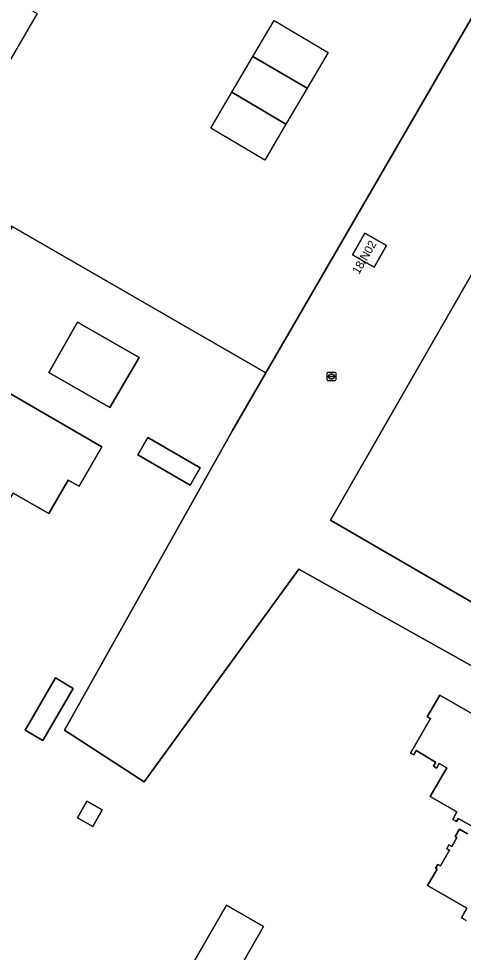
# Model space of a CAD drawing. Extents: x 156502 to 159075, y 384229 to 386100.
# Drawn here: x 157217.5 to 157270.5, y 385707.8 to 385818.9 of the extents above; entities that cross this region are included whole.
import ezdxf

# ---------------------------------------------------------------- set-up
doc = ezdxf.new("R2010")
doc.units = 0
for name, color, linetype in [('IMGEO_Erf', 7, 'Continuous'), ('IMGEO_Gemengd_bos', 7, 'Continuous'), ('IMGEO_Grasland_overig', 7, 'Continuous'), ('IMGEO_Hek', 7, 'Continuous'), ('IMGEO_Pand', 7, 'Continuous'), ('IMGEO_Pand_nummerreeks', 7, 'Continuous'), ('IMGEO_Pand_vergunning_verleend', 7, 'Continuous'), ('IMGEO_Rioolput', 7, 'Continuous')]:
    doc.layers.add(name, color=color, linetype=linetype)

msp = doc.modelspace()

# ---------------------------------------------------------------- linework, layer by layer
at = {"layer": 'IMGEO_Erf'}
for points in [[(157285.22, 385812.46), (157254.63, 385759.26), (157295.91, 385735.36)], [(157300.61, 385725.63), (157250.89, 385753.43), (157232.44, 385728.12), (157222.97, 385734.27), (157242.96, 385769.96), (157246.93, 385776.79), (157216.71, 385794.2), (157213.48, 385788.66), (157210.48, 385783.47), (157204.89, 385773.82), (157204.09, 385772.37), (157190.66, 385749.03), (157190.19, 385748.22), (157189.58, 385747.17), (157173.06, 385718.5), (157188.56, 385701.55)], [(157271.48, 385722.84), (157269.92, 385723.74), (157269.87, 385723.77), (157269.65, 385723.39), (157269.2, 385723.65), (157269.71, 385724.54), (157266.53, 385726.38), (157268.5, 385729.78), (157267.59, 385730.3), (157267.28, 385729.77), (157266.91, 385729.99), (157267.19, 385730.47), (157267.15, 385730.49), (157264.84, 385731.84), (157264.55, 385731.34), (157264.18, 385731.56), (157266.55, 385735.65), (157266.17, 385735.87), (157267.66, 385738.45), (157272.7, 385735.53)], [(157270.8, 385711.63), (157270.24, 385711.96), (157270.9, 385713.1), (157266.2, 385715.79), (157267.33, 385717.75), (157267.15, 385717.85), (157267.42, 385718.31), (157267.76, 385718.12), (157268.83, 385719.98), (157268.49, 385720.17), (157268.75, 385720.64), (157269.09, 385720.44), (157269.7, 385721.5), (157269.48, 385721.62), (157270, 385722.51), (157270.96, 385721.95)]]:
    msp.add_lwpolyline(points, dxfattribs=at)
for points in [[(157221.09, 385776.86), (157224.52, 385782.84), (157231.84, 385778.64), (157228.38, 385772.66)], [(157216.83, 385762.5), (157214.84, 385759.03), (157215.78, 385758.51), (157212.12, 385752.19), (157207.44, 385754.89), (157208.16, 385756.16), (157204.14, 385758.49), (157207.06, 385763.56), (157207.93, 385763.06), (157209.9, 385766.51), (157209.04, 385767.01), (157210.23, 385769.06), (157211.36, 385771.04), (157210.09, 385771.77), (157212.8, 385776.43), (157227.39, 385767.99), (157224.69, 385763.33), (157223.41, 385764.04), (157221.09, 385760.05)], [(157231.7, 385767.06), (157232.9, 385769.12), (157239.12, 385765.48), (157237.93, 385763.43)], [(157220.39, 385733.03), (157218.29, 385734.26), (157221.89, 385740.49), (157223.98, 385739.25)], [(157226.33, 385722.82), (157224.51, 385723.85), (157225.63, 385725.82), (157227.44, 385724.79)], [(157242.25, 385713.46), (157246.67, 385710.91), (157242.61, 385703.87), (157238.19, 385706.43)]]:
    msp.add_lwpolyline(points, close=True, dxfattribs=at)
at = {"layer": 'IMGEO_Gemengd_bos'}
for points in [[(157285.22, 385812.46), (157275.52, 385818.05), (157272.04, 385820.04), (157246.93, 385776.79), (157242.96, 385769.96), (157222.97, 385734.27), (157232.44, 385728.12), (157250.89, 385753.43), (157300.61, 385725.63), (157300.68, 385725.75), (157301.99, 385728.11), (157303.57, 385730.97), (157295.91, 385735.36), (157254.63, 385759.26)], [(157259.84, 385789.36), (157257.25, 385790.84), (157258.72, 385793.43), (157261.32, 385791.94)]]:
    msp.add_lwpolyline(points, close=True, dxfattribs=at)
at = {"layer": 'IMGEO_Grasland_overig'}
msp.add_lwpolyline([(157186.51, 385823.49), (157214.2, 385807.37), (157215.15, 385806.82), (157210.12, 385798.13), (157215.69, 385794.81), (157216.71, 385794.2), (157246.93, 385776.79), (157272.04, 385820.04)], dxfattribs=at)
at = {"layer": 'IMGEO_Hek'}
msp.add_lwpolyline([(157295.91, 385735.36), (157254.63, 385759.26), (157285.22, 385812.46)], dxfattribs=at)
at = {"layer": 'IMGEO_Pand'}
for points in [[(157259.84, 385789.36), (157261.32, 385791.94), (157258.72, 385793.43), (157257.25, 385790.84)], [(157231.84, 385778.64), (157224.52, 385782.84), (157221.09, 385776.86), (157228.38, 385772.66)], [(157227.39, 385767.99), (157212.8, 385776.43), (157210.09, 385771.77), (157211.36, 385771.04), (157210.23, 385769.06), (157209.04, 385767.01), (157209.9, 385766.51), (157207.93, 385763.06), (157207.06, 385763.56), (157204.14, 385758.49), (157208.16, 385756.16), (157207.44, 385754.89), (157212.12, 385752.19), (157215.78, 385758.51), (157214.84, 385759.03), (157216.83, 385762.5), (157221.09, 385760.05), (157223.41, 385764.04), (157224.69, 385763.33)], [(157232.9, 385769.12), (157231.7, 385767.06), (157237.93, 385763.43), (157239.12, 385765.48)], [(157221.89, 385740.49), (157218.29, 385734.26), (157220.39, 385733.03), (157223.98, 385739.25)], [(157224.51, 385723.85), (157226.33, 385722.82), (157227.44, 385724.79), (157225.63, 385725.82)], [(157246.67, 385710.91), (157242.25, 385713.46), (157238.19, 385706.43), (157242.61, 385703.87)]]:
    msp.add_lwpolyline(points, close=True, dxfattribs=at)
for points in [[(157272.7, 385735.53), (157267.66, 385738.45), (157266.17, 385735.87), (157266.55, 385735.65), (157264.18, 385731.56), (157264.55, 385731.34), (157264.84, 385731.84), (157267.15, 385730.49), (157267.19, 385730.47), (157266.91, 385729.99), (157267.28, 385729.77), (157267.59, 385730.3), (157268.5, 385729.78), (157266.53, 385726.38), (157269.71, 385724.54), (157269.2, 385723.65), (157269.65, 385723.39), (157269.87, 385723.77), (157269.92, 385723.74), (157271.48, 385722.84)], [(157270.96, 385721.95), (157270, 385722.51), (157269.48, 385721.62), (157269.7, 385721.5), (157269.09, 385720.44), (157268.75, 385720.64), (157268.49, 385720.17), (157268.83, 385719.98), (157267.76, 385718.12), (157267.42, 385718.31), (157267.15, 385717.85), (157267.33, 385717.75), (157266.2, 385715.79), (157270.9, 385713.1), (157270.24, 385711.96), (157270.8, 385711.63)]]:
    msp.add_lwpolyline(points, dxfattribs=at)
at = {"layer": 'IMGEO_Pand_vergunning_verleend'}
for points in [[(157204.02, 385820.18), (157207.73, 385826.55), (157209.87, 385825.3), (157216.64, 385821.35), (157219.71, 385819.56), (157216, 385813.2)], [(157245.41, 385814.46), (157247.93, 385818.72), (157254.37, 385814.92), (157251.86, 385810.66)], [(157242.9, 385810.2), (157245.41, 385814.46), (157251.86, 385810.66), (157249.34, 385806.39)], [(157240.38, 385805.93), (157242.9, 385810.2), (157249.34, 385806.39), (157246.83, 385802.13)]]:
    msp.add_lwpolyline(points, close=True, dxfattribs=at)
at = {"layer": 'IMGEO_Rioolput'}
for p, q in [((157254.25, 385775.95), (157254.25, 385776.8)), ((157254.33, 385776.88), (157255.18, 385776.88)), ((157254.51, 385776.37), (157254.51, 385776.38)), ((157254.95, 385776.33), (157254.55, 385776.33)), ((157254.56, 385776.42), (157254.95, 385776.42)), ((157254.74, 385776.65), (157254.77, 385776.65)), ((157254.76, 385776.1), (157254.74, 385776.1)), ((157255, 385776.38), (157255, 385776.37)), ((157255.26, 385776.8), (157255.26, 385775.95)), ((157255.18, 385775.87), (157254.33, 385775.87))]:
    msp.add_line(p, q, dxfattribs=at)
for points in [[(157254.25, 385775.95), (157254.25, 385776.8)], [(157254.33, 385776.88), (157255.18, 385776.88)], [(157255.26, 385776.8), (157255.26, 385775.95)], [(157255.18, 385775.87), (157254.33, 385775.87)]]:
    msp.add_lwpolyline(points, dxfattribs=at)
for centre, radius, start, end in [((157254.33, 385776.8), 0.0765, 91.552, 178.448), ((157254.33, 385776.8), 0.0765, 91.552, 178.448), ((157254.55, 385776.38), 0.0403, 85.8775, 175.7526), ((157254.55, 385776.37), 0.0366, 178.938, 274.7102), ((157254.96, 385776.38), 0.0386, 1.7309, 96.639), ((157254.95, 385776.37), 0.043, 264.8664, 352.4533), ((157255.18, 385776.8), 0.0765, 1.552, 88.448), ((157255.18, 385776.8), 0.0765, 1.552, 88.448), ((157254.33, 385775.95), 0.0765, 181.552, 268.448), ((157254.33, 385775.95), 0.0765, 181.552, 268.448), ((157255.18, 385775.95), 0.0765, 271.552, 358.448), ((157255.18, 385775.95), 0.0765, 271.552, 358.448)]:
    msp.add_arc(centre, radius, start, end, dxfattribs=at)
for centre, major_axis, ratio, start_param, end_param in [((157254.74, 385776.37), (-0.387, 0.002), 0.722429, 4.712389, 7.853982), ((157254.77, 385776.37), (-0.39, 0.002), 0.717154, 1.570796, 4.712389)]:
    msp.add_ellipse(centre, major_axis=major_axis, ratio=ratio, start_param=start_param, end_param=end_param, dxfattribs=at)

# ---------------------------------------------------------------- texts
at = {"layer": 'IMGEO_Pand_nummerreeks'}
msp.add_text('18/N02', height=1, rotation=60.1601, dxfattribs=at).set_placement((157258.03, 385788.44))

doc.saveas('drawing.dxf')
